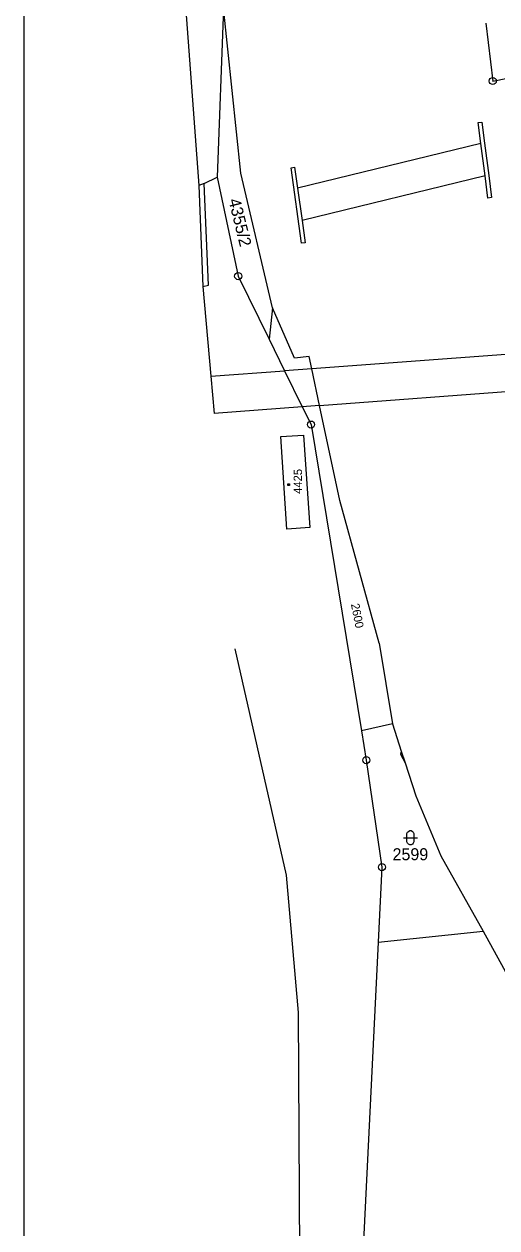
# Model space of a CAD drawing. Extents: x -468021 to -466942, y -1130484 to -1128584.
# Drawn here: x -468020.6 to -467953.5, y -1129179.8 to -1129009 of the extents above; entities that cross this region are included whole.
import ezdxf

# ---------------------------------------------------------------- set-up
doc = ezdxf.new("R2010")
doc.units = 0
doc.layers.add('Default', color=7, linetype='Continuous')
doc.layers.add('DKM', color=7, linetype='Continuous')

msp = doc.modelspace()

# ---------------------------------------------------------------- linework, layer by layer
at = {"layer": 'Default'}
msp.add_lwpolyline([(-468020.6, -1128583.91), (-466941.68, -1128583.91), (-466941.68, -1130484.41), (-468020.6, -1130484.41)], close=True, dxfattribs=at)
at = {"layer": 'DKM'}
for p, q in [((-467954.11, -1129017.05), (-467894.5, -1129004.79)), ((-467997.66, -1129007.04), (-467995.82, -1129031.85)), ((-467992.3, -1129006.68), (-467993.21, -1129030.69)), ((-467989.87, -1129030.11), (-467992.3, -1129006.68)), ((-467955.08, -1129008.85), (-467954.11, -1129017.05)), ((-467956.18, -1129022.94), (-467955.66, -1129022.87)), ((-467955.8, -1129025.92), (-467956.18, -1129022.94)), ((-467955.66, -1129022.87), (-467955.28, -1129025.85)), ((-467955.8, -1129025.92), (-467981.81, -1129032.26)), ((-467955.21, -1129030.51), (-467955.8, -1129025.92)), ((-467955.28, -1129025.85), (-467954.69, -1129030.44)), ((-467982.73, -1129029.36), (-467982.23, -1129029.29)), ((-467981.23, -1129040.05), (-467982.73, -1129029.36)), ((-467982.23, -1129029.29), (-467981.81, -1129032.26)), ((-467995.04, -1129031.58), (-467995.82, -1129031.85)), ((-467995.04, -1129031.58), (-467993.21, -1129030.69)), ((-467994.45, -1129045.99), (-467995.04, -1129031.58)), ((-467993.21, -1129030.69), (-467990.23, -1129044.73)), ((-467985.38, -1129049.21), (-467989.87, -1129030.11)), ((-467955.21, -1129030.51), (-467981.17, -1129036.85)), ((-467954.81, -1129033.65), (-467955.21, -1129030.51)), ((-467954.69, -1129030.44), (-467954.29, -1129033.58)), ((-467995.82, -1129031.85), (-467995.25, -1129046.22)), ((-467981.81, -1129032.26), (-467981.17, -1129036.85)), ((-467954.29, -1129033.58), (-467954.81, -1129033.65)), ((-467981.17, -1129036.85), (-467980.73, -1129039.98)), ((-467980.73, -1129039.98), (-467981.23, -1129040.05)), ((-467990.23, -1129044.73), (-467985.84, -1129053.67)), ((-467995.25, -1129046.22), (-467994.45, -1129045.99)), ((-467995.25, -1129046.22), (-467994.12, -1129058.93)), ((-467985.38, -1129049.21), (-467985.84, -1129053.67)), ((-467982.25, -1129056.35), (-467985.38, -1129049.21)), ((-467985.84, -1129053.67), (-467983.64, -1129058.17)), ((-467980.16, -1129056.12), (-467982.25, -1129056.35)), ((-467979.79, -1129057.88), (-467980.16, -1129056.12)), ((-467948.02, -1129055.55), (-467979.79, -1129057.88)), ((-467994.12, -1129058.93), (-467983.64, -1129058.17)), ((-467994.12, -1129058.93), (-467993.65, -1129064.2)), ((-467979.79, -1129057.88), (-467983.64, -1129058.17)), ((-467983.64, -1129058.17), (-467981.13, -1129063.26)), ((-467978.69, -1129063.08), (-467979.79, -1129057.88)), ((-467978.69, -1129063.08), (-467946.39, -1129060.65)), ((-467981.13, -1129063.26), (-467993.65, -1129064.2)), ((-467978.69, -1129063.08), (-467981.13, -1129063.26)), ((-467981.13, -1129063.26), (-467979.9, -1129065.78)), ((-467975.83, -1129076.57), (-467978.69, -1129063.08)), ((-467984.2, -1129067.49), (-467980.96, -1129067.28)), ((-467980.96, -1129067.28), (-467980.07, -1129080.4)), ((-467979.9, -1129065.78), (-467972.74, -1129109.25)), ((-467983.32, -1129080.62), (-467984.2, -1129067.49)), ((-467983.17, -1129074.21), (-467982.96, -1129074.21)), ((-467983.17, -1129074.42), (-467983.17, -1129074.21)), ((-467982.96, -1129074.21), (-467982.96, -1129074.42)), ((-467982.96, -1129074.42), (-467983.17, -1129074.42)), ((-467970.24, -1129096.78), (-467975.83, -1129076.57)), ((-467980.07, -1129080.4), (-467983.32, -1129080.62)), ((-467990.69, -1129097.61), (-467983.42, -1129129.72)), ((-467970.24, -1129096.78), (-467968.35, -1129108.25)), ((-467968.35, -1129108.25), (-467972.74, -1129109.25)), ((-467968.35, -1129108.25), (-467967.1, -1129112.1)), ((-467972.74, -1129109.25), (-467972.06, -1129113.39)), ((-467972.06, -1129113.39), (-467969.84, -1129128.57)), ((-467967.1, -1129112.1), (-467967.21, -1129112.54)), ((-467967.21, -1129112.54), (-467966.56, -1129113.79)), ((-467967.1, -1129112.1), (-467966.56, -1129113.79)), ((-467966.56, -1129113.79), (-467965.05, -1129118.44)), ((-467965.05, -1129118.44), (-467961.48, -1129126.98)), ((-467966.29, -1129123.79), (-467966.19, -1129123.59)), ((-467966.29, -1129124.99), (-467966.29, -1129123.79)), ((-467966.19, -1129123.59), (-467966.09, -1129123.49)), ((-467966.09, -1129123.49), (-467965.89, -1129123.39)), ((-467965.89, -1129123.39), (-467965.69, -1129123.39)), ((-467965.69, -1129123.39), (-467965.49, -1129123.49)), ((-467965.49, -1129123.49), (-467965.39, -1129123.59)), ((-467965.39, -1129123.59), (-467965.29, -1129123.79)), ((-467965.29, -1129123.79), (-467965.29, -1129124.99)), ((-467966.79, -1129124.39), (-467964.79, -1129124.39)), ((-467966.19, -1129125.19), (-467966.29, -1129124.99)), ((-467966.09, -1129125.29), (-467966.19, -1129125.19)), ((-467965.89, -1129125.39), (-467966.09, -1129125.29)), ((-467965.69, -1129125.39), (-467965.89, -1129125.39)), ((-467965.49, -1129125.29), (-467965.69, -1129125.39)), ((-467965.39, -1129125.19), (-467965.49, -1129125.29)), ((-467965.29, -1129124.99), (-467965.39, -1129125.19)), ((-467961.48, -1129126.98), (-467955.46, -1129137.67)), ((-467969.84, -1129128.57), (-467970.37, -1129139.22)), ((-467983.42, -1129129.72), (-467981.74, -1129149.21)), ((-467970.37, -1129139.22), (-467955.46, -1129137.67)), ((-467955.46, -1129137.67), (-467941.47, -1129163.21)), ((-467970.37, -1129139.22), (-467972.74, -1129187.19)), ((-467981.74, -1129149.21), (-467981.31, -1129215.59))]:
    msp.add_line(p, q, dxfattribs=at)
for centre, radius in [((-467954.11, -1129017.05), 0.5), ((-467954.11, -1129017.05), 0.01), ((-467990.23, -1129044.73), 0.5), ((-467990.23, -1129044.73), 0.01), ((-467979.9, -1129065.78), 0.5), ((-467979.9, -1129065.78), 0.01), ((-467972.06, -1129113.39), 0.5), ((-467972.06, -1129113.39), 0.01), ((-467969.84, -1129128.57), 0.5), ((-467969.84, -1129128.57), 0.01)]:
    msp.add_circle(centre, radius, dxfattribs=at)

# ---------------------------------------------------------------- texts
for s, height, rotation, p in [('4355/2', 1.7, 283.8847, (-467991.62, -1129033.93)), ('4425', 1.19, 90, (-467981.17, -1129075.62)), ('2600', 1.19, 281.206, (-467974.24, -1129091.28))]:
    msp.add_text(s, height=height, rotation=rotation, dxfattribs=at).set_placement(p)
msp.add_text('2599', height=1.7, dxfattribs=at).set_placement((-467968.33, -1129127.59))

doc.saveas('drawing.dxf')
